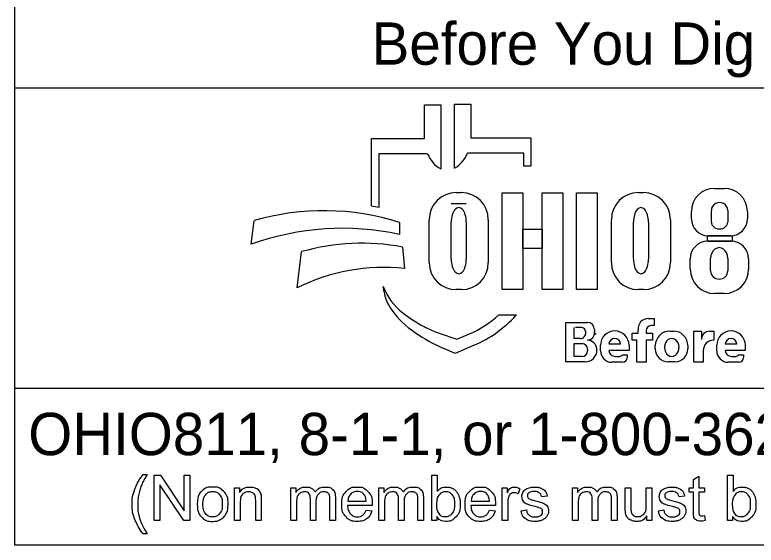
# Model space of a CAD drawing. Extents: x 0 to 34, y 0 to 22.
# Drawn here: x 2.978 to 5.431, y 2.143 to 3.897 of the extents above; entities that cross this region are included whole.
import ezdxf

# ---------------------------------------------------------------- set-up
doc = ezdxf.new("R2010")
doc.units = 0
doc.layers.add('SH_Border', color=7, linetype='Continuous')
doc.layers.add('SH_Cut_Line', color=7, linetype='Continuous')

msp = doc.modelspace()

# ---------------------------------------------------------------- linework, layer by layer
at = {"layer": 'SH_Border'}
for p, q in [((4.3335, 3.4883), (4.3335, 3.5998)), ((4.3335, 3.5998), (4.3872, 3.5998)), ((4.3872, 3.5998), (4.3872, 3.3877)), ((4.4329, 3.39), (4.4329, 3.6021)), ((4.4329, 3.6021), (4.4865, 3.6021)), ((4.4865, 3.6021), (4.4865, 3.4906)), ((4.1576, 3.2644), (4.1576, 3.4883)), ((4.1576, 3.4883), (4.3335, 3.4883)), ((4.4865, 3.4906), (4.6857, 3.4906)), ((4.6857, 3.4906), (4.6857, 3.3968)), ((4.1828, 3.4369), (4.1828, 3.26)), ((4.3439, 3.4369), (4.1828, 3.4369)), ((4.6625, 3.4392), (4.4761, 3.4392)), ((4.6625, 3.3968), (4.6625, 3.4392)), ((4.6857, 3.3968), (4.6625, 3.3968)), ((5.2931, 3.3231), (5.3258, 3.3231)), ((4.4385, 3.3091), (4.4551, 3.3091)), ((5.0416, 3.3091), (5.0581, 3.3091)), ((4.4718, 3.2721), (4.422, 3.2721)), ((5.2168, 3.2225), (5.2168, 3.2468)), ((5.283, 3.2111), (5.283, 3.2504)), ((5.3371, 3.2504), (5.3371, 3.2111)), ((5.4022, 3.2468), (5.4022, 3.2225)), ((3.7602, 3.1381), (3.7696, 3.2162)), ((4.3491, 3.0776), (4.3491, 3.2196)), ((4.5445, 3.2196), (4.5445, 3.0776)), ((4.9521, 3.0776), (4.9521, 3.2196)), ((5.1476, 3.2196), (5.1476, 3.0776)), ((4.2509, 3.2097), (4.2509, 3.1709)), ((4.422, 3.089), (4.422, 3.2114)), ((4.4718, 3.2114), (4.4718, 3.089)), ((5.025, 3.089), (5.025, 3.2114)), ((5.0748, 3.2114), (5.0748, 3.089)), ((5.3462, 3.1665), (5.2728, 3.1665)), ((5.271, 3.1482), (5.3483, 3.1482)), ((4.2608, 3.1291), (4.2671, 3.0582)), ((3.912, 2.9936), (3.9267, 3.1137)), ((5.2131, 3.0563), (5.2131, 3.0903)), ((5.2806, 3.0503), (5.2806, 3.0912)), ((5.3374, 3.0912), (5.3374, 3.0503)), ((5.4062, 3.0903), (5.4062, 3.0563)), ((4.1997, 2.9807), (4.1967, 2.9986)), ((4.4551, 2.9882), (4.4385, 2.9882)), ((5.0581, 2.9882), (5.0416, 2.9882)), ((5.3252, 2.9753), (5.2941, 2.9753)), ((4.58, 2.9048), (4.6375, 2.9048)), ((4.8013, 2.749), (4.8013, 2.8798)), ((4.8013, 2.8798), (4.8725, 2.8798)), ((5.0739, 2.8926), (5.0934, 2.8926)), ((5.0934, 2.8926), (5.0934, 2.8696)), ((4.8293, 2.8263), (4.8293, 2.8632)), ((4.8545, 2.8632), (4.8332, 2.8632)), ((4.8963, 2.856), (4.8963, 2.8481)), ((5.0406, 2.8442), (5.0406, 2.8546)), ((5.0667, 2.8526), (5.0667, 2.8442)), ((5.0934, 2.8691), (5.0832, 2.8691)), ((5.1451, 2.8508), (5.1573, 2.8508)), ((5.2254, 2.7478), (5.2254, 2.8505)), ((5.2254, 2.8505), (5.2499, 2.8505)), ((5.2499, 2.8505), (5.2499, 2.8237)), ((5.2772, 2.8505), (5.291, 2.8505)), ((5.291, 2.8505), (5.291, 2.8209)), ((4.3816, 2.8444), (4.441, 2.8239)), ((4.441, 2.8239), (4.4821, 2.8417)), ((4.8487, 2.8263), (4.8293, 2.8263)), ((5.0213, 2.8212), (5.0213, 2.8442)), ((5.0213, 2.8442), (5.0406, 2.8442)), ((5.0667, 2.8442), (5.0883, 2.8442)), ((5.0883, 2.8442), (5.0883, 2.8212)), ((4.4983, 2.8044), (4.435, 2.7769)), ((4.8293, 2.7669), (4.8293, 2.8097)), ((4.8293, 2.8097), (4.8548, 2.8097)), ((4.9159, 2.7858), (4.9159, 2.8042)), ((4.9824, 2.8082), (4.9439, 2.8082)), ((5.0104, 2.8042), (5.0104, 2.7866)), ((5.0362, 2.8212), (5.0213, 2.8212)), ((5.0362, 2.7478), (5.0362, 2.8212)), ((5.0883, 2.8212), (5.0667, 2.8212)), ((5.0667, 2.8212), (5.0667, 2.7478)), ((5.0973, 2.7922), (5.0973, 2.8029)), ((5.2051, 2.8029), (5.2051, 2.7922)), ((5.3008, 2.7858), (5.3008, 2.8042)), ((5.3674, 2.8082), (5.3288, 2.8082)), ((5.3953, 2.8042), (5.3953, 2.7866)), ((4.435, 2.7769), (4.3976, 2.7934)), ((4.8729, 2.7916), (4.8729, 2.7853)), ((4.9043, 2.7887), (4.9043, 2.7884)), ((5.0104, 2.7866), (4.944, 2.7866)), ((4.9876, 2.7729), (5.0045, 2.7729)), ((5.0045, 2.7729), (5.0045, 2.7631)), ((5.2559, 2.786), (5.2559, 2.7478)), ((5.3953, 2.7866), (5.3289, 2.7866)), ((5.3725, 2.7729), (5.3894, 2.7729)), ((5.3894, 2.7729), (5.3894, 2.7631)), ((4.865, 2.749), (4.8013, 2.749)), ((4.8546, 2.7669), (4.8293, 2.7669)), ((4.9649, 2.7673), (4.979, 2.7673)), ((5.1623, 2.7494), (5.1401, 2.7494)), ((5.3498, 2.7673), (5.3639, 2.7673)), ((4.9892, 2.7478), (4.9538, 2.7478)), ((5.0667, 2.7478), (5.0362, 2.7478)), ((5.2559, 2.7478), (5.2254, 2.7478)), ((5.3742, 2.7478), (5.3388, 2.7478))]:
    msp.add_line(p, q, dxfattribs=at)
for points in [[(4.591, 3.3081), (4.6589, 3.3081), (4.6589, 2.9881), (4.591, 2.9881)], [(4.7231, 3.3081), (4.7911, 3.3081), (4.7911, 2.9881), (4.7231, 2.9881)], [(4.8364, 3.3081), (4.9052, 3.3081), (4.9052, 2.9881), (4.8364, 2.9881)], [(4.6589, 3.1882), (4.7231, 3.1882), (4.7231, 3.1242), (4.6589, 3.1242)], [(5.2706, 3.1665), (5.3523, 3.1665), (5.3523, 3.1481), (5.2706, 3.1481)]]:
    msp.add_lwpolyline(points, close=True, dxfattribs=at)
for points in [[(3.4021, 2.3766), (3.4153, 2.3766)], [(3.4389, 2.2239), (3.4389, 2.3741), (3.4592, 2.3741), (3.5382, 2.2561), (3.5382, 2.3741), (3.5572, 2.3741), (3.5572, 2.2239), (3.5369, 2.2239), (3.4579, 2.3419), (3.4579, 2.2239), (3.4389, 2.2239)], [(4.3743, 2.2239), (4.3573, 2.2239), (4.3573, 2.3741), (4.3757, 2.3741), (4.3757, 2.3206)], [(5.2233, 2.2558), (5.2233, 2.3185), (5.2097, 2.3185), (5.2097, 2.3328), (5.2233, 2.3328), (5.2233, 2.3597), (5.2417, 2.3708), (5.2417, 2.3328), (5.2601, 2.3328), (5.2601, 2.3185), (5.2417, 2.3185), (5.2417, 2.2547)], [(5.3534, 2.2239), (5.3363, 2.2239), (5.3363, 2.3741), (5.3548, 2.3741), (5.3548, 2.3206)], [(3.7048, 2.2239), (3.7048, 2.3328), (3.7214, 2.3328), (3.7214, 2.3173)], [(3.8912, 2.2239), (3.8912, 2.3328), (3.9077, 2.3328), (3.9077, 2.3174)], [(4.1826, 2.2239), (4.1826, 2.3328), (4.1991, 2.3328), (4.1991, 2.3174)], [(4.5904, 2.2239), (4.5904, 2.3328), (4.607, 2.3328), (4.607, 2.3163)], [(4.8236, 2.2239), (4.8236, 2.3328), (4.8401, 2.3328), (4.8401, 2.3174)], [(4.9979, 2.2654), (4.9979, 2.3328), (5.0164, 2.3328), (5.0164, 2.2724)], [(5.0676, 2.2745), (5.0676, 2.3328), (5.0861, 2.3328), (5.0861, 2.2239), (5.0696, 2.2239)], [(4.6495, 2.3293), (4.643, 2.3122)], [(3.7233, 2.2833), (3.7233, 2.2239), (3.7048, 2.2239)], [(3.7932, 2.2908), (3.7932, 2.2239), (3.7748, 2.2239), (3.7748, 2.2901)], [(3.9743, 2.2871), (3.9743, 2.2239), (3.9559, 2.2239), (3.9559, 2.2946)], [(4.0388, 2.2986), (4.0388, 2.2239), (4.0203, 2.2239), (4.0203, 2.2924)], [(4.0799, 2.2887), (4.1406, 2.2887)], [(4.2657, 2.2871), (4.2657, 2.2239), (4.2473, 2.2239), (4.2473, 2.2946)], [(4.3301, 2.2986), (4.3301, 2.2239), (4.3117, 2.2239), (4.3117, 2.2924)], [(4.4879, 2.2887), (4.5486, 2.2887)], [(4.7394, 2.3046), (4.7213, 2.3022)], [(4.9067, 2.2871), (4.9067, 2.2239), (4.8883, 2.2239), (4.8883, 2.2946)], [(4.9711, 2.2986), (4.9711, 2.2239), (4.9527, 2.2239), (4.9527, 2.2924)], [(5.194, 2.3046), (5.1759, 2.3022)], [(3.9097, 2.2803), (3.9097, 2.2239), (3.8912, 2.2239)], [(4.16, 2.2736), (4.0788, 2.2736)], [(4.1404, 2.2591), (4.1595, 2.2567)], [(4.201, 2.2803), (4.201, 2.2239), (4.1826, 2.2239)], [(4.568, 2.2736), (4.4868, 2.2736)], [(4.5484, 2.2591), (4.5675, 2.2567)], [(4.6088, 2.2809), (4.6088, 2.2239), (4.5904, 2.2239)], [(4.653, 2.2564), (4.6712, 2.2593)], [(4.842, 2.2803), (4.842, 2.2239), (4.8236, 2.2239)], [(5.1076, 2.2564), (5.1258, 2.2593)], [(4.3743, 2.2375), (4.3743, 2.2239)], [(5.0696, 2.2239), (5.0696, 2.24)], [(5.2601, 2.2404), (5.2628, 2.2241)], [(5.3534, 2.2375), (5.3534, 2.2239)], [(3.4153, 2.1798), (3.4021, 2.1798)]]:
    msp.add_lwpolyline(points, dxfattribs=at)
for centre, radius, start, end in [((4.4353, 3.4736), 0.0985, 201.9296, 240.7469), ((4.3847, 3.476), 0.0985, 299.2531, 338.0704), ((5.2931, 3.2468), 0.0763, 90, 180), ((5.3258, 3.2468), 0.0763, 0, 90), ((4.4385, 3.2196), 0.0895, 90, 180), ((4.4551, 3.2196), 0.0895, 0, 90), ((5.0416, 3.2196), 0.0895, 90, 180), ((5.0581, 3.2196), 0.0895, 0, 90), ((4.0295, 2.4554), 0.8191, 79.2074, 81.0007), ((3.9997, 2.4302), 0.8191, 72.1402, 106.3144), ((5.2728, 3.2225), 0.056, 180, 270), ((5.3462, 3.2225), 0.056, 270, 0), ((4.0628, 2.2991), 0.8919, 77.8238, 109.8274), ((4.1267, 2.4094), 0.7322, 79.44, 105.8467), ((5.271, 3.0903), 0.0579, 90, 180), ((5.3483, 3.0903), 0.0579, 0, 90), ((4.4385, 3.0776), 0.0895, 180, 270), ((4.4551, 3.0776), 0.0895, 270, 0), ((5.0416, 3.0776), 0.0895, 180, 270), ((5.0581, 3.0776), 0.0895, 270, 0), ((4.1987, 2.4262), 0.6357, 83.8248, 116.8021), ((5.2941, 3.0563), 0.081, 180, 270), ((5.3252, 3.0563), 0.081, 270, 0), ((4.3841, 3.0707), 0.2008, 201.0457, 232.5314), ((4.341, 3.0048), 0.1433, 189.6817, 216.0884), ((4.4747, 3.1022), 0.3088, 216.0884, 235.7167), ((4.5766, 3.3219), 0.5173, 232.5314, 241.794), ((4.3387, 3.1722), 0.3602, 293.4582, 312.0712), ((4.3387, 3.1722), 0.401, 293.4582, 317.8286), ((4.8725, 2.856), 0.0238, 0, 90), ((5.0739, 2.859), 0.0335, 90, 187.5187), ((4.6412, 3.3465), 0.6044, 235.7167, 246.2325), ((4.4914, 3.1631), 0.3371, 241.794, 250.9821), ((4.8505, 2.8463), 0.0169, 357.8325, 90), ((4.8721, 2.8453), 0.0243, 270, 6.6529), ((4.9631, 2.8042), 0.0473, 0, 180), ((5.0832, 2.8526), 0.0165, 90, 180), ((5.1451, 2.8029), 0.0478, 90, 180), ((5.1573, 2.8029), 0.0478, 0, 90), ((5.2768, 2.8237), 0.0269, 89.2449, 180), ((5.3481, 2.8042), 0.0473, 0, 180), ((4.8487, 2.845), 0.0187, 270, 2.0582), ((4.8827, 2.8438), 0.0175, 347.4023, 0), ((4.9632, 2.8072), 0.0193, 2.9632, 177.0368), ((5.3481, 2.8072), 0.0193, 2.9632, 177.0368), ((4.8548, 2.7916), 0.0181, 0, 90), ((4.8722, 2.7889), 0.0321, 4.0748, 90), ((5.2908, 2.786), 0.0349, 89.6033, 180), ((4.8546, 2.7853), 0.0184, 270, 0), ((4.865, 2.7884), 0.0393, 270, 0), ((4.8714, 2.7887), 0.033, 0, 11.7502), ((4.9538, 2.7858), 0.038, 180, 270), ((4.9649, 2.7883), 0.021, 184.827, 270), ((4.979, 2.7767), 0.00938, 270, 335.9979), ((5.1401, 2.7922), 0.0428, 180, 270), ((5.1623, 2.7922), 0.0428, 270, 0), ((5.3388, 2.7858), 0.038, 180, 270), ((5.3498, 2.7883), 0.021, 184.827, 270), ((5.3639, 2.7767), 0.00938, 270, 335.9979), ((4.9892, 2.7631), 0.0152, 270, 0), ((5.3742, 2.7631), 0.0152, 270, 0)]:
    msp.add_arc(centre, radius, start, end, dxfattribs=at)
for centre, major_axis, ratio, start_param, end_param in [((5.31, 3.2504), (0.0271, 0), 0.969373, 0, 3.141593), ((4.4469, 3.2114), (0, 0.0484), 0.514403, 4.712389, 7.853982), ((5.0499, 3.2114), (0, 0.0484), 0.514403, 4.712389, 7.853982), ((5.31, 3.2111), (0.0271, 0), 0.818453, 3.141593, 6.283185), ((5.309, 3.0912), (0, 0.0358), 0.794529, 4.712389, 7.853982), ((4.4469, 3.089), (0, 0.0484), 0.514403, 1.570796, 4.712389), ((5.0499, 3.089), (0, 0.0484), 0.514403, 1.570796, 4.712389), ((5.309, 3.0503), (0.0284, 0), 0.959837, 3.141593, 6.283185), ((5.1517, 2.7976), (0, 0.029), 0.832186, 4.712389, 7.853982), ((5.1517, 2.7976), (0, 0.0302), 0.797287, 1.570796, 4.712389)]:
    msp.add_ellipse(centre, major_axis=major_axis, ratio=ratio, start_param=start_param, end_param=end_param, dxfattribs=at)
for points in [[(3.4021, 2.1798), (3.3869, 2.199), (3.3763, 2.2248), (3.3657, 2.2506), (3.3657, 2.2783), (3.3657, 2.3026), (3.3736, 2.325), (3.3829, 2.3509), (3.4021, 2.3766)], [(3.4153, 2.3766), (3.4029, 2.3553), (3.3989, 2.3462), (3.3927, 2.332), (3.3891, 2.3167), (3.3847, 2.2975), (3.3847, 2.2782), (3.3847, 2.2289), (3.4153, 2.1798)], [(3.5814, 2.2783), (3.5814, 2.3085), (3.5981, 2.3231), (3.6122, 2.3352), (3.6323, 2.3352), (3.6547, 2.3352), (3.669, 2.3205), (3.6832, 2.3058), (3.6832, 2.2799), (3.6832, 2.2589), (3.6769, 2.2469), (3.6706, 2.2348), (3.6586, 2.2282), (3.6466, 2.2215), (3.6323, 2.2215), (3.6095, 2.2215), (3.5954, 2.2362), (3.5814, 2.2508), (3.5814, 2.2783)], [(3.7214, 2.3173), (3.7334, 2.3352), (3.756, 2.3352), (3.7659, 2.3352), (3.7741, 2.3316), (3.7823, 2.3281), (3.7864, 2.3224), (3.7905, 2.3166), (3.7922, 2.3087), (3.7932, 2.3036), (3.7932, 2.2908)], [(3.9077, 2.3174), (3.9128, 2.3254), (3.9214, 2.3303), (3.9299, 2.3352), (3.9407, 2.3352), (3.9528, 2.3352), (3.9606, 2.3301), (3.9683, 2.3251), (3.9715, 2.3161), (3.9844, 2.3352), (4.0051, 2.3352), (4.0213, 2.3352), (4.03, 2.3262), (4.0388, 2.3172), (4.0388, 2.2986)], [(4.1595, 2.2567), (4.155, 2.24), (4.1428, 2.2307), (4.1306, 2.2215), (4.1117, 2.2215), (4.0878, 2.2215), (4.0738, 2.2362), (4.0598, 2.2509), (4.0598, 2.2774), (4.0598, 2.3049), (4.074, 2.32), (4.0881, 2.3352), (4.1106, 2.3352), (4.1324, 2.3352), (4.1463, 2.3203), (4.1601, 2.3055), (4.1601, 2.2785), (4.1601, 2.2769), (4.16, 2.2736)], [(4.1991, 2.3174), (4.2042, 2.3254), (4.2127, 2.3303), (4.2212, 2.3352), (4.2321, 2.3352), (4.2442, 2.3352), (4.2519, 2.3301), (4.2597, 2.3251), (4.2628, 2.3161), (4.2758, 2.3352), (4.2965, 2.3352), (4.3127, 2.3352), (4.3214, 2.3262), (4.3301, 2.3172), (4.3301, 2.2986)], [(4.3757, 2.3206), (4.3874, 2.3352), (4.4055, 2.3352), (4.4155, 2.3352), (4.4245, 2.3311), (4.4335, 2.3271), (4.4392, 2.3198), (4.445, 2.3124), (4.4483, 2.3021), (4.4516, 2.2918), (4.4516, 2.28), (4.4516, 2.252), (4.4378, 2.2368), (4.4239, 2.2215), (4.4046, 2.2215), (4.3853, 2.2215), (4.3743, 2.2375)], [(4.5675, 2.2567), (4.563, 2.24), (4.5508, 2.2307), (4.5386, 2.2215), (4.5196, 2.2215), (4.4958, 2.2215), (4.4818, 2.2362), (4.4678, 2.2509), (4.4678, 2.2774), (4.4678, 2.3049), (4.482, 2.32), (4.4961, 2.3352), (4.5186, 2.3352), (4.5404, 2.3352), (4.5543, 2.3203), (4.5681, 2.3055), (4.5681, 2.2785), (4.5681, 2.2769), (4.568, 2.2736)], [(4.607, 2.3163), (4.6133, 2.3278), (4.6187, 2.3315), (4.6241, 2.3352), (4.6305, 2.3352), (4.6398, 2.3352), (4.6495, 2.3293)], [(4.6712, 2.2593), (4.6727, 2.2483), (4.6798, 2.2425), (4.6868, 2.2366), (4.6995, 2.2366), (4.7122, 2.2366), (4.7184, 2.2418), (4.7245, 2.247), (4.7245, 2.254), (4.7245, 2.2602), (4.7191, 2.2638), (4.7153, 2.2663), (4.7002, 2.2701), (4.6799, 2.2752), (4.672, 2.2789), (4.6642, 2.2827), (4.6601, 2.2893), (4.6561, 2.2959), (4.6561, 2.3038), (4.6561, 2.3111), (4.6594, 2.3173), (4.6628, 2.3235), (4.6685, 2.3276), (4.6728, 2.3308), (4.6803, 2.333), (4.6877, 2.3352), (4.6962, 2.3352), (4.709, 2.3352), (4.7187, 2.3315), (4.7284, 2.3278), (4.733, 2.3215), (4.7377, 2.3152), (4.7394, 2.3046)], [(4.8401, 2.3174), (4.8452, 2.3254), (4.8537, 2.3303), (4.8622, 2.3352), (4.8731, 2.3352), (4.8852, 2.3352), (4.8929, 2.3301), (4.9007, 2.3251), (4.9038, 2.3161), (4.9168, 2.3352), (4.9375, 2.3352), (4.9537, 2.3352), (4.9624, 2.3262), (4.9711, 2.3172), (4.9711, 2.2986)], [(5.1258, 2.2593), (5.1273, 2.2483), (5.1343, 2.2425), (5.1414, 2.2366), (5.154, 2.2366), (5.1668, 2.2366), (5.1729, 2.2418), (5.1791, 2.247), (5.1791, 2.254), (5.1791, 2.2602), (5.1736, 2.2638), (5.1698, 2.2663), (5.1548, 2.2701), (5.1345, 2.2752), (5.1266, 2.2789), (5.1188, 2.2827), (5.1147, 2.2893), (5.1107, 2.2959), (5.1107, 2.3038), (5.1107, 2.3111), (5.114, 2.3173), (5.1173, 2.3235), (5.1231, 2.3276), (5.1274, 2.3308), (5.1348, 2.333), (5.1423, 2.3352), (5.1508, 2.3352), (5.1636, 2.3352), (5.1733, 2.3315), (5.183, 2.3278), (5.1876, 2.3215), (5.1922, 2.3152), (5.194, 2.3046)], [(5.3548, 2.3206), (5.3664, 2.3352), (5.3846, 2.3352), (5.3946, 2.3352), (5.4036, 2.3311), (5.4125, 2.3271), (5.4183, 2.3198), (5.4241, 2.3124), (5.4274, 2.3021), (5.4306, 2.2918), (5.4306, 2.28), (5.4306, 2.252), (5.4168, 2.2368), (5.403, 2.2215), (5.3836, 2.2215), (5.3644, 2.2215), (5.3534, 2.2375)], [(3.6003, 2.2783), (3.6003, 2.2574), (3.6094, 2.247), (3.6185, 2.2366), (3.6323, 2.2366), (3.646, 2.2366), (3.6551, 2.2471), (3.6642, 2.2575), (3.6642, 2.279), (3.6642, 2.2991), (3.6551, 2.3095), (3.6459, 2.3199), (3.6323, 2.3199), (3.6185, 2.3199), (3.6094, 2.3096), (3.6003, 2.2992), (3.6003, 2.2783)], [(3.7748, 2.2901), (3.7748, 2.3013), (3.7726, 2.3069), (3.7705, 2.3125), (3.765, 2.3158), (3.7595, 2.3191), (3.7521, 2.3191), (3.7404, 2.3191), (3.7318, 2.3117), (3.7233, 2.3042), (3.7233, 2.2833)], [(3.9559, 2.2946), (3.9559, 2.3069), (3.9514, 2.313), (3.9469, 2.3191), (3.9366, 2.3191), (3.9288, 2.3191), (3.9222, 2.315), (3.9156, 2.311), (3.9126, 2.3031), (3.9097, 2.2952), (3.9097, 2.2803)], [(4.0203, 2.2924), (4.0203, 2.3035), (4.0185, 2.3083), (4.0168, 2.3132), (4.012, 2.3162), (4.0073, 2.3191), (4.001, 2.3191), (3.9895, 2.3191), (3.9819, 2.3115), (3.9743, 2.3039), (3.9743, 2.2871)], [(4.1406, 2.2887), (4.1394, 2.3025), (4.1337, 2.3094), (4.1249, 2.3201), (4.1108, 2.3201), (4.0981, 2.3201), (4.0894, 2.3115), (4.0808, 2.303), (4.0799, 2.2887)], [(4.2473, 2.2946), (4.2473, 2.3069), (4.2428, 2.313), (4.2383, 2.3191), (4.228, 2.3191), (4.2202, 2.3191), (4.2136, 2.315), (4.207, 2.311), (4.204, 2.3031), (4.201, 2.2952), (4.201, 2.2803)], [(4.3117, 2.2924), (4.3117, 2.3035), (4.3099, 2.3083), (4.3081, 2.3132), (4.3034, 2.3162), (4.2987, 2.3191), (4.2923, 2.3191), (4.2809, 2.3191), (4.2733, 2.3115), (4.2657, 2.3039), (4.2657, 2.2871)], [(4.3741, 2.2792), (4.3741, 2.2596), (4.3794, 2.2509), (4.3881, 2.2366), (4.4029, 2.2366), (4.415, 2.2366), (4.4238, 2.2471), (4.4326, 2.2576), (4.4326, 2.2784), (4.4326, 2.2998), (4.4241, 2.3099), (4.4157, 2.3201), (4.4038, 2.3201), (4.3917, 2.3201), (4.3829, 2.3096), (4.3741, 2.299), (4.3741, 2.2792)], [(4.5486, 2.2887), (4.5474, 2.3025), (4.5417, 2.3094), (4.5328, 2.3201), (4.5188, 2.3201), (4.5061, 2.3201), (4.4974, 2.3115), (4.4888, 2.303), (4.4879, 2.2887)], [(4.643, 2.3122), (4.6363, 2.3162), (4.6295, 2.3162), (4.6235, 2.3162), (4.6187, 2.3125), (4.6139, 2.3089), (4.6119, 2.3024), (4.6088, 2.2926), (4.6088, 2.2809)], [(4.7213, 2.3022), (4.7201, 2.3106), (4.7142, 2.3153), (4.7083, 2.3201), (4.6975, 2.3201), (4.6848, 2.3201), (4.6794, 2.3159), (4.6739, 2.3116), (4.6739, 2.306), (4.6739, 2.3024), (4.6762, 2.2995), (4.6785, 2.2966), (4.6833, 2.2946), (4.686, 2.2936), (4.6996, 2.2899), (4.7192, 2.2847), (4.7269, 2.2813), (4.7347, 2.278), (4.7391, 2.2717), (4.7435, 2.2653), (4.7435, 2.2559), (4.7435, 2.2467), (4.7381, 2.2386), (4.7327, 2.2304), (4.7226, 2.226), (4.7124, 2.2215), (4.6996, 2.2215), (4.6784, 2.2215), (4.6672, 2.2303), (4.6561, 2.2391), (4.653, 2.2564)], [(4.8883, 2.2946), (4.8883, 2.3069), (4.8838, 2.313), (4.8793, 2.3191), (4.869, 2.3191), (4.8612, 2.3191), (4.8546, 2.315), (4.848, 2.311), (4.845, 2.3031), (4.842, 2.2952), (4.842, 2.2803)], [(4.9527, 2.2924), (4.9527, 2.3035), (4.9509, 2.3083), (4.9491, 2.3132), (4.9444, 2.3162), (4.9397, 2.3191), (4.9333, 2.3191), (4.9219, 2.3191), (4.9143, 2.3115), (4.9067, 2.3039), (4.9067, 2.2871)], [(5.1759, 2.3022), (5.1747, 2.3106), (5.1688, 2.3153), (5.1629, 2.3201), (5.1521, 2.3201), (5.1394, 2.3201), (5.1339, 2.3159), (5.1285, 2.3116), (5.1285, 2.306), (5.1285, 2.3024), (5.1308, 2.2995), (5.133, 2.2966), (5.1378, 2.2946), (5.1406, 2.2936), (5.1542, 2.2899), (5.1737, 2.2847), (5.1815, 2.2813), (5.1893, 2.278), (5.1937, 2.2717), (5.1981, 2.2653), (5.1981, 2.2559), (5.1981, 2.2467), (5.1927, 2.2386), (5.1873, 2.2304), (5.1772, 2.226), (5.167, 2.2215), (5.1542, 2.2215), (5.1329, 2.2215), (5.1218, 2.2303), (5.1107, 2.2391), (5.1076, 2.2564)], [(5.3532, 2.2792), (5.3532, 2.2596), (5.3585, 2.2509), (5.3672, 2.2366), (5.382, 2.2366), (5.3941, 2.2366), (5.4029, 2.2471), (5.4116, 2.2576), (5.4116, 2.2784), (5.4116, 2.2998), (5.4032, 2.3099), (5.3948, 2.3201), (5.3828, 2.3201), (5.3708, 2.3201), (5.362, 2.3096), (5.3532, 2.299), (5.3532, 2.2792)], [(4.0788, 2.2736), (4.0799, 2.2557), (4.089, 2.2462), (4.0981, 2.2366), (4.1117, 2.2366), (4.1219, 2.2366), (4.1291, 2.242), (4.1362, 2.2473), (4.1404, 2.2591)], [(4.4868, 2.2736), (4.4879, 2.2557), (4.497, 2.2462), (4.5061, 2.2366), (4.5197, 2.2366), (4.5299, 2.2366), (4.537, 2.242), (4.5442, 2.2473), (4.5484, 2.2591)], [(5.0696, 2.24), (5.0569, 2.2215), (5.0351, 2.2215), (5.0255, 2.2215), (5.0171, 2.2252), (5.0088, 2.2289), (5.0047, 2.2345), (5.0007, 2.2401), (4.9991, 2.2482), (4.9979, 2.2536), (4.9979, 2.2654)], [(5.0164, 2.2724), (5.0164, 2.258), (5.0175, 2.253), (5.0192, 2.2457), (5.0249, 2.2416), (5.0305, 2.2374), (5.0388, 2.2374), (5.0471, 2.2374), (5.0543, 2.2417), (5.0616, 2.2459), (5.0646, 2.2533), (5.0676, 2.2606), (5.0676, 2.2745)], [(5.2628, 2.2241), (5.255, 2.2224), (5.2488, 2.2224), (5.2388, 2.2224), (5.2333, 2.2256), (5.2278, 2.2288), (5.2255, 2.234), (5.2233, 2.2392), (5.2233, 2.2558)], [(5.2417, 2.2547), (5.2417, 2.2468), (5.2427, 2.2445), (5.2436, 2.2423), (5.2458, 2.2409), (5.248, 2.2396), (5.2521, 2.2396), (5.2551, 2.2396), (5.2601, 2.2404)]]:
    msp.add_open_spline(points, degree=3, dxfattribs=at)
at = {"layer": 'SH_Cut_Line'}
for p, q in [((2.9775, 2.1428), (2.9775, 4.4803)), ((2.9775, 3.6553), (7.2275, 3.6553)), ((7.2275, 2.6607), (2.9775, 2.6607)), ((7.2275, 2.1428), (2.9775, 2.1428))]:
    msp.add_line(p, q, dxfattribs=at)

# ---------------------------------------------------------------- texts
at = {"layer": 'SH_Border'}
for s, p in [('Before You Dig', (4.1583, 3.7321)), ('OHIO811, 8-1-1, or 1-800-362-2764', (3.022, 2.4406))]:
    msp.add_text(s, height=0.14, dxfattribs=at).set_placement(p)

doc.saveas('drawing.dxf')
